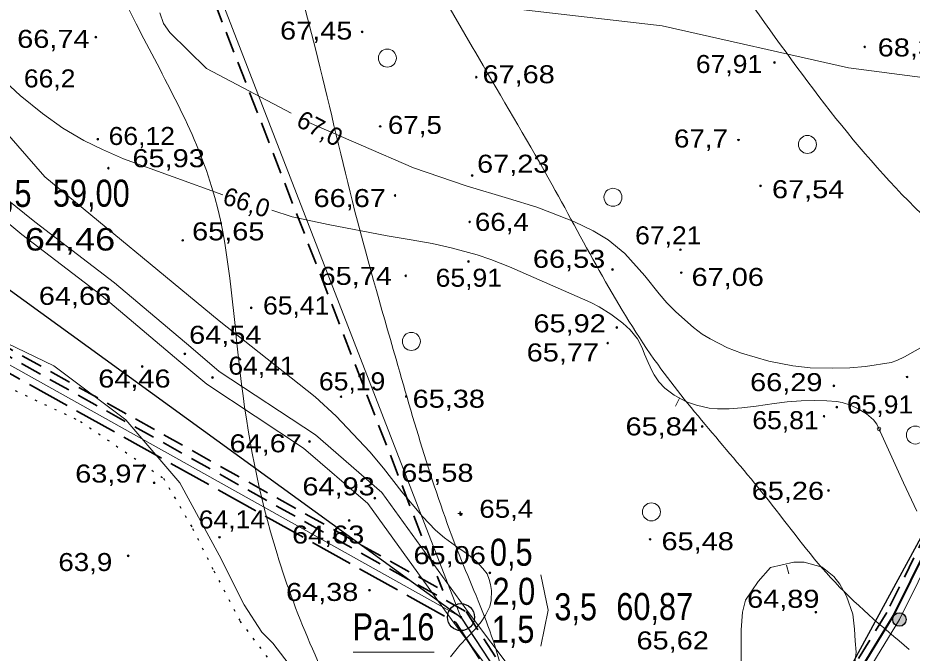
# Model space of a CAD drawing. Extents: x 628176 to 629009, y 6439913 to 6440496.
# Drawn here: x 628423 to 628522.3, y 6440153.1 to 6440223.6 of the extents above; entities that cross this region are included whole.
import ezdxf
from ezdxf.enums import TextEntityAlignment as Align

# ---------------------------------------------------------------- set-up
doc = ezdxf.new("R2010")
doc.units = 0
doc.header["$LTSCALE"] = 0.8
doc.header["$PDMODE"] = 32
doc.header["$PDSIZE"] = 0.4
for name, pattern in [('DOTTED', [1.5, 0.3, -1.2]), ('LONG_DASHED', [7.5, 6, -1.5]), ('MEDIUM_DASHED', [4.5, 3, -1.5])]:
    doc.linetypes.add(name, pattern=pattern)
for name, color, linetype, lineweight in [('1', 7, 'Continuous', 13), ('10', 7, 'Continuous', 25), ('11', 7, 'Continuous', 13), ('12', 7, 'Continuous', 13), ('14', 7, 'Continuous', 25), ('16', 7, 'Continuous', 13), ('21', 7, 'MEDIUM_DASHED', 35), ('3', 7, 'Continuous', 13)]:
    doc.layers.add(name, color=color, linetype=linetype, lineweight=lineweight)

msp = doc.modelspace()

# ---------------------------------------------------------------- hatches: boundary and pattern name
at = {"layer": '1'}
for points in [[(628431.7655, 6440221.5, 1), (628431.5655, 6440221.5, 1)], [(628461.3301, 6440222.0679, 1), (628461.1301, 6440222.0679, 1)], [(628517.1461, 6440220.4038, 1), (628516.9461, 6440220.4038, 1)], [(628507.1214, 6440218.6695, 1), (628506.9214, 6440218.6695, 1)], [(628474.0153, 6440217.0519, 1), (628473.8153, 6440217.0519, 1)], [(628463.3331, 6440211.5884, 1), (628463.1331, 6440211.5884, 1)], [(628431.971, 6440210.1551, 1), (628431.771, 6440210.1551, 1)], [(628503.1247, 6440210.0752, 1), (628502.9247, 6440210.0752, 1)], [(628433.1511, 6440206.9486, 1), (628432.9511, 6440206.9486, 1)], [(628473.551, 6440206.1226, 1), (628473.351, 6440206.1226, 1)], [(628505.588, 6440204.9758, 1), (628505.388, 6440204.9758, 1)], [(628464.9847, 6440203.9064, 1), (628464.7847, 6440203.9064, 1)], [(628473.2742, 6440200.9778, 1), (628473.0742, 6440200.9778, 1)], [(628441.4116, 6440198.9322, 1), (628441.2116, 6440198.9322, 1)], [(628496.6772, 6440197.8959, 1), (628496.4772, 6440197.8959, 1)], [(628473.1327, 6440196.5865, 1), (628472.9327, 6440196.5865, 1)], [(628489.1359, 6440195.7002, 1), (628488.9359, 6440195.7002, 1)], [(628496.7735, 6440195.3478, 1), (628496.5735, 6440195.3478, 1)], [(628466.171, 6440194.9958, 1), (628465.971, 6440194.9958, 1)], [(628433.0964, 6440193.5352, 1), (628432.8964, 6440193.5352, 1)], [(628449.0188, 6440191.4455, 1), (628448.8188, 6440191.4455, 1)], [(628489.6061, 6440189.2554, 1), (628489.4061, 6440189.2554, 1)], [(628488.603, 6440187.5318, 1), (628488.403, 6440187.5318, 1)], [(628441.6444, 6440186.3201, 1), (628441.4444, 6440186.3201, 1)], [(628436.9164, 6440184.9227, 1), (628436.7164, 6440184.9227, 1)], [(628444.7146, 6440183.7124, 1), (628444.5146, 6440183.7124, 1)], [(628521.8533, 6440183.765, 1), (628521.6533, 6440183.765, 1)], [(628513.7287, 6440182.7766, 1), (628513.5287, 6440182.7766, 1)], [(628458.9871, 6440181.5784, 1), (628458.7871, 6440181.5784, 1)], [(628466.233, 6440181.6092, 1), (628466.033, 6440181.6092, 1)], [(628514.0425, 6440180.4252, 1), (628513.8425, 6440180.4252, 1)], [(628512.6279, 6440179.4027, 1), (628512.4279, 6440179.4027, 1)], [(628499.1078, 6440178.2775, 1), (628498.9078, 6440178.2775, 1)], [(628455.4905, 6440176.6067, 1), (628455.2905, 6440176.6067, 1)], [(628438.2238, 6440172.0215, 1), (628438.0238, 6440172.0215, 1)], [(628513.1225, 6440171.1642, 1), (628512.9225, 6440171.1642, 1)], [(628462.7425, 6440170.3143, 1), (628462.5425, 6440170.3143, 1)], [(628472.229, 6440168.6031, 1), (628472.029, 6440168.6031, 1)], [(628472.3344, 6440168.5073, 1), (628472.1344, 6440168.5073, 1)], [(628459.8898, 6440167.8399, 1), (628459.6898, 6440167.8399, 1)], [(628445.4972, 6440165.9628, 1), (628445.2972, 6440165.9628, 1)], [(628493.3088, 6440165.7432, 1), (628493.1088, 6440165.7432, 1)], [(628435.3569, 6440163.9046, 1), (628435.1569, 6440163.9046, 1)], [(628475.5183, 6440162.0132, 1), (628475.3183, 6440162.0132, 1)], [(628462.1504, 6440160.0873, 1), (628461.9504, 6440160.0873, 1)], [(628511.7276, 6440157.6404, 1), (628511.5276, 6440157.6404, 1)], [(628472.3061, 6440157.1027, 1), (628472.1061, 6440157.1027, 1)]]:
    msp.add_hatch(color=256, dxfattribs=at).paths.add_polyline_path(points)
at = {"layer": '10'}
msp.add_hatch(color=256, dxfattribs=at).paths.add_polyline_path([(628521.6531, 6440156.8433, 1), (628520.1531, 6440156.8433, 1)])

# ---------------------------------------------------------------- linework, layer by layer
at = {"layer": '1'}
for p, q in [((628424.88, 6440201), (628421.64, 6440203.63)), ((628423.46, 6440199.59), (628420.56, 6440201.95)), ((628433.73, 6440194.21), (628424.88, 6440201)), ((628463.43, 6440170.93), (628473.05, 6440157.63)), ((628461.85, 6440169.7), (628471.36, 6440156.57)), ((628472.13, 6440168.6), (628471.88, 6440168.6)), ((628472.13, 6440168.6), (628472.13, 6440168.85)), ((628472.13, 6440168.6), (628472.13, 6440168.35)), ((628472.13, 6440168.6), (628472.38, 6440168.6)), ((628473.05, 6440157.63), (628483.84, 6440143.29)), ((628471.36, 6440156.57), (628482.04, 6440142.4))]:
    msp.add_line(p, q, dxfattribs=at)
for points in [[(628461.85, 6440169.7), (628454.72, 6440175.86), (628443.97, 6440182.95), (628440.88, 6440185.57), (628432.26, 6440192.86), (628423.46, 6440199.59)], [(628463.43, 6440170.93), (628456.06, 6440177.35), (628445.35, 6440184.39), (628442.21, 6440187.07), (628433.73, 6440194.21)]]:
    msp.add_lwpolyline(points, dxfattribs=at)
at = {"layer": '1', "linetype": 'DOTTED', "lineweight": 25}
msp.add_lwpolyline([(628352.66, 6440194.21), (628361.18, 6440196.45), (628372.08, 6440198.4), (628381.65, 6440198.63), (628389.03, 6440197.45), (628395.92, 6440195.41), (628401.35, 6440193.56), (628413.35, 6440188.21), (628419.46, 6440183.8), (628429.96, 6440178.83), (628439.17, 6440172.52), (628442.41, 6440166.94), (628444.75, 6440162.25), (628447.66, 6440156.67), (628451.45, 6440151.65), (628455.36, 6440146.51), (628457.42, 6440140.66), (628458.82, 6440136.02), (628463.06, 6440130.1), (628466.63, 6440124.3), (628470.09, 6440119.39), (628472.43, 6440114.37), (628474.33, 6440109.9)], dxfattribs=at)
at = {"layer": '1'}
for centre, radius in [((628431.6655, 6440221.5), 0.1), ((628461.2301, 6440222.0679), 0.1), ((628517.0461, 6440220.4038), 0.1), ((628464.0339, 6440219.1709), 1), ((628507.0214, 6440218.6695), 0.1), ((628473.9153, 6440217.0519), 0.1), ((628463.2331, 6440211.5884), 0.1), ((628510.6823, 6440209.5747), 1), ((628431.871, 6440210.1551), 0.1), ((628503.0247, 6440210.0752), 0.1), ((628433.0511, 6440206.9486), 0.1), ((628473.451, 6440206.1226), 0.1), ((628489.0908, 6440203.7103), 1), ((628505.488, 6440204.9758), 0.1), ((628464.8847, 6440203.9064), 0.1), ((628473.1742, 6440200.9778), 0.1), ((628441.3116, 6440198.9322), 0.1), ((628496.5772, 6440197.8959), 0.1), ((628473.0327, 6440196.5865), 0.1), ((628489.0359, 6440195.7002), 0.1), ((628496.6735, 6440195.3478), 0.1), ((628466.071, 6440194.9958), 0.1), ((628432.9964, 6440193.5352), 0.1), ((628448.9188, 6440191.4455), 0.1), ((628466.6996, 6440187.7166), 1), ((628489.5061, 6440189.2554), 0.1), ((628488.503, 6440187.5318), 0.1), ((628441.5444, 6440186.3201), 0.1), ((628436.8164, 6440184.9227), 0.1), ((628444.6146, 6440183.7124), 0.1), ((628521.7533, 6440183.765), 0.1), ((628513.6287, 6440182.7766), 0.1), ((628458.8871, 6440181.5784), 0.1), ((628466.133, 6440181.6092), 0.1), ((628513.9425, 6440180.4252), 0.1), ((628512.5279, 6440179.4027), 0.1), ((628499.0078, 6440178.2775), 0.1), ((628522.6776, 6440177.3207), 1), ((628455.3905, 6440176.6067), 0.1), ((628438.1238, 6440172.0215), 0.1), ((628513.0225, 6440171.1642), 0.1), ((628462.6425, 6440170.3143), 0.1), ((628493.3558, 6440168.7907), 1), ((628472.129, 6440168.6031), 0.1), ((628472.2344, 6440168.5073), 0.1), ((628459.7898, 6440167.8399), 0.1), ((628445.3972, 6440165.9628), 0.1), ((628493.2088, 6440165.7432), 0.1), ((628435.2569, 6440163.9046), 0.1), ((628475.4183, 6440162.0132), 0.1), ((628462.0504, 6440160.0873), 0.1), ((628511.6276, 6440157.6404), 0.1), ((628472.2061, 6440157.1027), 0.1)]:
    msp.add_circle(centre, radius, dxfattribs=at)
at = {"layer": '10'}
msp.add_circle((628520.9031, 6440156.8433), 0.75, dxfattribs=at)
at = {"layer": '11'}
for points in [[(628479.31, 6440413.61), (628403.76, 6440281.52), (628439.01, 6440242.62), (628472.21, 6440157.1)], [(628547.63, 6440210.77), (628520.9, 6440156.84), (628497.5, 6440118.54)], [(628320.67, 6440172), (628398.18, 6440198.42), (628472.21, 6440157.1), (628497.5, 6440118.54)]]:
    msp.add_lwpolyline(points, dxfattribs=at)
at = {"layer": '12'}
msp.add_line((628460.24, 6440153.23), (628469.25, 6440153.23), dxfattribs=at)
msp.add_lwpolyline([(628481.08, 6440161.79), (628481.89, 6440157.86), (628481.08, 6440153.89)], dxfattribs=at)
at = {"layer": '12', "lineweight": 25}
msp.add_circle((628472.2061, 6440157.1027), 1.5, dxfattribs=at)
at = {"layer": '14'}
for points in [[(628648.46, 6440349.59), (628617.39, 6440307.28), (628547.63, 6440210.77), (628497.5, 6440118.54), (628474.19, 6440080.39)], [(628326.62, 6440323.6), (628400.29, 6440209.22), (628472.21, 6440157.1), (628497.5, 6440118.54), (628498.85, 6440116.47)]]:
    msp.add_lwpolyline(points, dxfattribs=at)
at = {"layer": '16'}
for points in [[(628409.9, 6440254.58), (628412.29, 6440252.6), (628420.3, 6440245.33), (628427.75, 6440237.7), (628436.13, 6440222.98), (628444.52, 6440204.92), (628447.68, 6440184.24), (628451.78, 6440164.12), (628460.72, 6440143.45), (628472.64, 6440122.77), (628478.97, 6440106.2), (628480.84, 6440088.32)], [(628435.66, 6440253.61), (628435.76, 6440253.53), (628440.6, 6440249.8), (628446.19, 6440242.17), (628451.59, 6440233.41), (628456.06, 6440220.19), (628460.16, 6440203.24), (628465, 6440185.73), (628472.27, 6440163.38), (628475.81, 6440154.44), (628479.91, 6440135.81), (628483.63, 6440121.84), (628486.42, 6440113.09), (628492.01, 6440103.59)], [(628489.38, 6440249.57), (628495.6, 6440238.31), (628503.56, 6440226.46), (628524.07, 6440201.18), (628533.26, 6440193.04), (628542.28, 6440184.38)], [(628468.19, 6440229.57), (628474.69, 6440218.33), (628482.33, 6440205.1), (628494.06, 6440185.17), (628506.35, 6440170.08), (628513.25, 6440161.52), (628522, 6440153.51)]]:
    msp.add_spline(points, degree=3, dxfattribs=at)
at = {"layer": '21'}
for points in [[(628476.73, 6440410.71), (628402.77, 6440281.42), (628438.32, 6440242.19), (628470.2, 6440160.05)], [(628546.49, 6440212.09), (628519.5, 6440157.62), (628496.99, 6440120.78)], [(628321.66, 6440174.2), (628398.34, 6440200.16), (628470.2, 6440160.05)], [(628321.72, 6440173.24), (628398.26, 6440199.29), (628472.77, 6440157.71), (628496.99, 6440120.78)]]:
    msp.add_lwpolyline(points, dxfattribs=at)
at = {"layer": '21', "linetype": 'Continuous', "lineweight": 40}
msp.add_lwpolyline([(628546.94, 6440211.19), (628520.2, 6440157.23), (628496.82, 6440118.96)], dxfattribs=at)
at = {"layer": '21', "linetype": 'LONG_DASHED'}
msp.add_lwpolyline([(628323.6, 6440172.11), (628398.09, 6440197.56), (628471.64, 6440156.5), (628496.07, 6440119.27)], dxfattribs=at)
at = {"layer": '3'}
for p, q in [((628438.76, 6440224.19), (628439.19, 6440223)), ((628475, 6440225), (628494.57, 6440222.74)), ((628494.57, 6440222.74), (628515.25, 6440218.07)), ((628453.35, 6440213.04), (628443.95, 6440218)), ((628421.11, 6440217), (628423.25, 6440215)), ((628423.25, 6440215), (628425.75, 6440213)), ((628425.75, 6440213), (628428, 6440211.4)), ((628428, 6440211.4), (628430.33, 6440210)), ((628466.93, 6440207), (628455.32, 6440212)), ((628434.75, 6440208), (628445.75, 6440204)), ((628466.93, 6440207), (628472.79, 6440205)), ((628451.21, 6440202.27), (628453.48, 6440201.55)), ((628464, 6440199.42), (628466.69, 6440199)), ((628471.14, 6440198.11), (628474, 6440197.33)), ((628477.6, 6440196), (628486.3, 6440192.19)), ((628520.63, 6440185.61), (628520, 6440185.37)), ((628515.4, 6440184.79), (628513.43, 6440184.73)), ((628517.15, 6440184.93), (628515.4, 6440184.79)), ((628517.15, 6440184.93), (628520, 6440185.37)), ((628496.02, 6440180.53), (628496.49, 6440181.41)), ((628512.84, 6440181.11), (628511.43, 6440181.15)), ((628513.92, 6440181.04), (628512.84, 6440181.11)), ((628517.26, 6440179.66), (628518.04, 6440179)), ((628518.04, 6440179), (628518.39, 6440178.54)), ((628518.39, 6440178.54), (628518.64, 6440178)), ((628508.37, 6440162.87), (628508.63, 6440161.91)), ((628475.5, 6440160.73), (628475.61, 6440160.05)), ((628475.58, 6440158.94), (628475.61, 6440160.05)), ((628474.46, 6440156.57), (628474.94, 6440157.31)), ((628472.09, 6440153.98), (628473.79, 6440155.78)), ((628473.79, 6440155.78), (628474.46, 6440156.57)), ((628471.06, 6440152.71), (628472.09, 6440153.98))]:
    msp.add_line(p, q, dxfattribs=at)
for points in [[(628398.04, 6440220.93), (628402, 6440222), (628406.22, 6440222.56), (628410, 6440222.28), (628412.96, 6440220.93), (628415.96, 6440218), (628418.98, 6440214), (628426, 6440206)], [(628439.19, 6440223), (628439.89, 6440222), (628443.95, 6440218)], [(628515.25, 6440218.07), (628523.48, 6440217), (628532.28, 6440216.56)], [(628430.33, 6440210), (628432.41, 6440209), (628434.75, 6440208)], [(628426, 6440206), (628445.35, 6440190), (628456, 6440181.57), (628458.36, 6440179.41)], [(628472.79, 6440205), (628477.5, 6440203.57), (628480.62, 6440202.6), (628482.26, 6440202), (628484.81, 6440201), (628486.9, 6440200), (628488.54, 6440199), (628490.4, 6440197.47), (628492.64, 6440195), (628494.23, 6440193), (628495.09, 6440192), (628496.08, 6440191), (628498.03, 6440189.26), (628499, 6440188.52), (628499.87, 6440188), (628501.81, 6440187), (628503.36, 6440186.4), (628506.41, 6440185.51), (628509.06, 6440185), (628511, 6440184.78), (628513.43, 6440184.73)], [(628453.48, 6440201.55), (628457.48, 6440200.68), (628464, 6440199.42)], [(628466.69, 6440199), (628469, 6440198.58), (628471.14, 6440198.11)], [(628477.6, 6440196), (628475.54, 6440196.79), (628474, 6440197.33)], [(628406.22, 6440195), (628427, 6440185), (628435, 6440179), (628441, 6440172), (628445.36, 6440164)], [(628520.63, 6440185.61), (628521.48, 6440186), (628523.24, 6440187), (628525.88, 6440189), (628528.65, 6440191), (628531, 6440192.55), (628533.55, 6440194)], [(628486.3, 6440192.19), (628486.69, 6440192), (628487.54, 6440191.55), (628488.84, 6440190.72), (628490.19, 6440189.74), (628490.99, 6440189), (628491.8, 6440188), (628492.35, 6440187), (628492.61, 6440186.31), (628493, 6440185.38), (628493.44, 6440184.41), (628493.66, 6440184), (628494.18, 6440183.24), (628494.85, 6440182.51), (628495.88, 6440181.74), (628497.25, 6440181), (628498.35, 6440180.62), (628499.79, 6440180.32), (628500.71, 6440180.22), (628502, 6440180.24), (628503.41, 6440180.34), (628505, 6440180.53), (628507, 6440180.82), (628508.43, 6440181), (628509.99, 6440181.13), (628511.43, 6440181.15)], [(628513.92, 6440181.04), (628514.55, 6440180.93), (628515.46, 6440180.64), (628516.33, 6440180.22), (628517.26, 6440179.66)], [(628475.5, 6440160.73), (628475.35, 6440161.29), (628475.11, 6440161.9), (628474.63, 6440162.52), (628473.89, 6440163.3), (628473.05, 6440164.01), (628471.59, 6440165.03), (628470.39, 6440165.92), (628469.39, 6440166.77), (628467.95, 6440168.26), (628465.65, 6440171.02), (628463.62, 6440173.63), (628462.09, 6440175.47), (628458.36, 6440179.41)], [(628522.85, 6440168.85), (628521.36, 6440172), (628518.39, 6440178.54)], [(628445.36, 6440164), (628448.12, 6440158.47), (628450.1, 6440155.43), (628451.32, 6440154.21), (628454.36, 6440150.26), (628456.79, 6440146.15), (628458.01, 6440142.2), (628459.23, 6440138.25), (628461.81, 6440133.99), (628464.7, 6440130.49), (628468.35, 6440125.32), (628469.72, 6440122.28), (628472.91, 6440117.11), (628476, 6440111.03)], [(628503.31, 6440151.87), (628503.31, 6440155.71), (628503.49, 6440157.66), (628503.8, 6440159), (628505.2, 6440161.07), (628506.6, 6440162.6), (628509.16, 6440163.21), (628510.32, 6440163.21), (628512.33, 6440162.66), (628513.61, 6440161.62), (628514.28, 6440160.77), (628515.01, 6440159.43), (628515.74, 6440157.42), (628515.92, 6440155.77), (628515.99, 6440154.49), (628516.11, 6440153.21), (628515.92, 6440151.75)], [(628474.94, 6440157.31), (628475.42, 6440158.27), (628475.58, 6440158.94)]]:
    msp.add_lwpolyline(points, dxfattribs=at)
msp.add_point((628518.64, 6440178), dxfattribs=at)

# ---------------------------------------------------------------- texts
at = {"layer": '1'}
for s, height, width, p in [('67,45', 2, 1.2, (628452.12, 6440221.22)), ('66,74', 2, 1.2, (628422.93, 6440220.3)), ('68,38', 2, 1.2, (628518.49, 6440219.35)), ('67,91', 2, 1.1, (628498.3, 6440217.51)), ('67,68', 2, 1.2, (628474.6, 6440216.37)), ('66,2', 2, 1.1, (628423.67, 6440215.91)), ('67,5', 2, 1.15, (628464.1, 6440210.75)), ('66,12', 2, 1.1, (628433.08, 6440209.52)), ('67,7', 2, 1.15, (628495.87, 6440209.24)), ('65,93', 2, 1.2, (628435.73, 6440207.05)), ('67,23', 2, 1.2, (628474, 6440206.44)), ('67,54', 2, 1.2, (628506.75, 6440203.61)), ('66,67', 2, 1.2, (628455.84, 6440202.63)), ('66,4', 2, 1.15, (628473.76, 6440199.98)), ('64,46', 2.5, 1.2, (628423.77, 6440197.8)), ('65,65', 2, 1.2, (628442.35, 6440198.93)), ('67,21', 2, 1.1, (628491.55, 6440198.49)), ('66,53', 2, 1.2, (628480.2, 6440195.88)), ('65,74', 2, 1.2, (628456.51, 6440193.99)), ('65,91', 2, 1.1, (628469.4, 6440193.78)), ('67,06', 2, 1.2, (628497.82, 6440193.87)), ('64,66', 2, 1.2, (628425.33, 6440191.77)), ('65,41', 2, 1.1, (628450.23, 6440190.7)), ('65,92', 2, 1.2, (628480.26, 6440188.72)), ('64,54', 2, 1.2, (628442.02, 6440187.45)), ('65,77', 2, 1.2, (628479.51, 6440185.49)), ('64,41', 2, 1.1, (628446.38, 6440184.02)), ('64,46', 2, 1.2, (628431.93, 6440182.59)), ('65,19', 2, 1.1, (628456.44, 6440182.28)), ('66,29', 2, 1.2, (628504.32, 6440182.19)), ('65,38', 2, 1.2, (628466.84, 6440180.35)), ('65,91', 2, 1.1, (628515.07, 6440179.71)), ('65,81', 2, 1.1, (628504.57, 6440177.97)), ('65,84', 2, 1.2, (628490.49, 6440177.28)), ('64,67', 2, 1.2, (628446.51, 6440175.4)), ('63,97', 2, 1.2, (628429.37, 6440172.04)), ('65,58', 2, 1.2, (628465.57, 6440172.13)), ('64,93', 2, 1.2, (628454.6, 6440170.62)), ('65,26', 2, 1.2, (628504.5, 6440170.13)), ('65,4', 2, 1.15, (628474.25, 6440168.13)), ('64,14', 2, 1.1, (628443.09, 6440166.95)), ('64,63', 2, 1.2, (628453.45, 6440165.27)), ('65,48', 2, 1.2, (628494.48, 6440164.53)), ('65,06', 2, 1.2, (628466.94, 6440162.99)), ('63,9', 2, 1.15, (628427.5, 6440162.22)), ('64,38', 2, 1.2, (628452.78, 6440158.9)), ('64,89', 2, 1.2, (628503.99, 6440158.14)), ('65,62', 2, 1.2, (628491.71, 6440153.52))]:
    msp.add_text(s, height=height, dxfattribs=dict(at, width=width)).set_placement(p)
at = {"layer": '11', "width": 0.85}
msp.add_text('0,5', height=3, dxfattribs=at).set_placement((628477.795, 6440162.81), align=Align.CENTER)
at = {"layer": '12', "width": 0.85}
for s, p in [('4,5', (628422.145, 6440202.64)), ('59,00', (628431.155, 6440202.67)), ('2,0', (628478.085, 6440158.47)), ('3,5', (628484.95, 6440156.75)), ('60,87', (628493.725, 6440156.78)), ('Pa-16', (628464.72, 6440154.53)), ('1,5', (628478, 6440154.25))]:
    msp.add_text(s, height=3, dxfattribs=at).set_placement(p, align=Align.CENTER)
at = {"layer": '3'}
for s, rotation, p in [('67,0', 332.177, (628453.77, 6440211.69)), ('66,0', 342.38, (628445.62, 6440202.99))]:
    msp.add_text(s, height=2, rotation=rotation, dxfattribs=at).set_placement(p)

doc.saveas('drawing.dxf')
